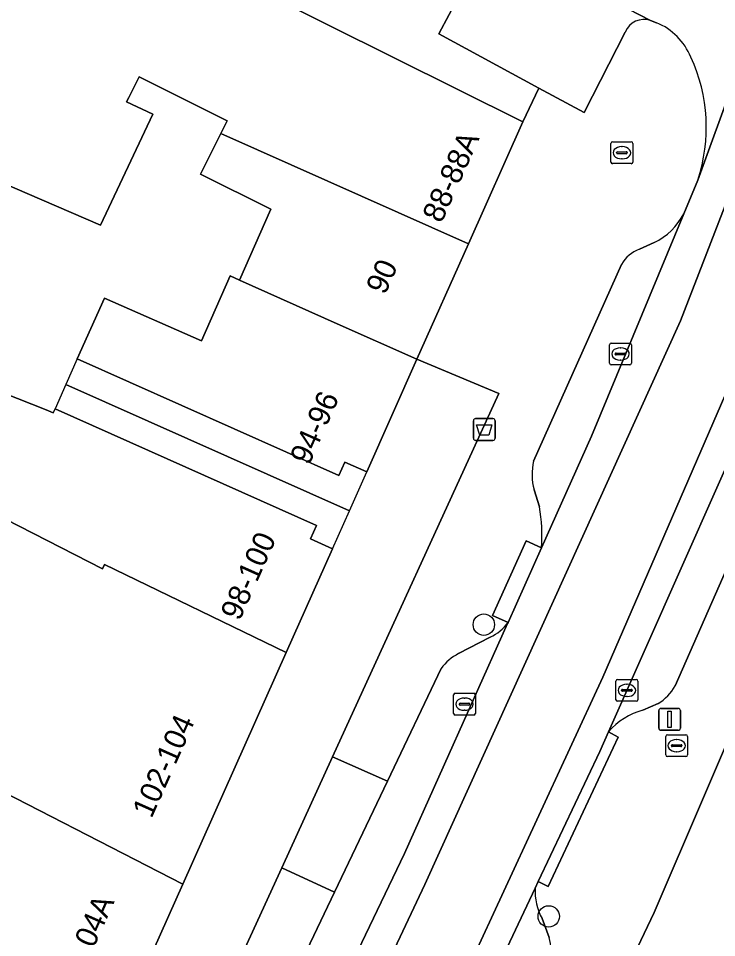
# Model space of a CAD drawing. Extents: x 160349 to 161355, y 381727 to 382854.
# Drawn here: x 160832.36 to 160864.31, y 382310.89 to 382352.95 of the extents above; entities that cross this region are included whole.
import ezdxf

# ---------------------------------------------------------------- set-up
doc = ezdxf.new("R2010")
doc.units = 0
for name, color, linetype in [('IMGEO_Afvalbak', 7, 'Continuous'), ('IMGEO_Boom', 7, 'Continuous'), ('IMGEO_Brandkraan', 7, 'Continuous'), ('IMGEO_Erf', 7, 'Continuous'), ('IMGEO_Kolk', 7, 'Continuous'), ('IMGEO_Lichtmast', 7, 'Continuous'), ('IMGEO_Pand', 7, 'Continuous'), ('IMGEO_Pand_nummerreeks', 7, 'Continuous'), ('IMGEO_Pand_overbouw', 7, 'Continuous'), ('IMGEO_Parkeervlak_open', 7, 'Continuous'), ('IMGEO_Rijbaan_lokaal_gesloten', 7, 'Continuous'), ('IMGEO_Rijbaan_lokaal_open', 7, 'Continuous'), ('IMGEO_Voetpad_open', 7, 'Continuous')]:
    doc.layers.add(name, color=color, linetype=linetype)

msp = doc.modelspace()

# ---------------------------------------------------------------- linework, layer by layer
at = {"layer": 'IMGEO_Afvalbak'}
for p, q in [((160853.179, 382333.741), (160853.179, 382334.541)), ((160853.179, 382334.541), (160853.179, 382333.741)), ((160853.279, 382334.641), (160854.069, 382334.641)), ((160854.069, 382334.641), (160853.279, 382334.641)), ((160854.169, 382334.541), (160854.169, 382333.741)), ((160854.169, 382333.741), (160854.169, 382334.541)), ((160854.069, 382333.641), (160853.279, 382333.641)), ((160853.279, 382333.641), (160854.069, 382333.641))]:
    msp.add_line(p, q, dxfattribs=at)
msp.add_lwpolyline([(160853.322, 382334.355), (160854.026, 382334.355), (160853.877, 382333.885), (160853.471, 382333.885), (160853.322, 382334.355)], dxfattribs=at)
for centre, start, end in [((160853.279, 382334.541), 90, 180), ((160853.279, 382334.541), 90, 180), ((160854.069, 382334.541), 0, 90), ((160854.069, 382334.541), 360, 90), ((160853.279, 382333.741), 180, 270), ((160853.279, 382333.741), 180, 270), ((160854.069, 382333.741), 270, 0), ((160854.069, 382333.741), 270, 0)]:
    msp.add_arc(centre, 0.1, start, end, dxfattribs=at)
at = {"layer": 'IMGEO_Boom'}
for centre in [(160853.654, 382325.214), (160856.624, 382311.862)]:
    msp.add_circle(centre, 0.489, dxfattribs=at)
at = {"layer": 'IMGEO_Brandkraan'}
for p, q in [((160859.472, 382346.381), (160859.472, 382347.233)), ((160859.547, 382347.307), (160860.399, 382347.307)), ((160860.473, 382347.233), (160860.473, 382346.381)), ((160859.731, 382346.801), (160859.731, 382346.813)), ((160860.169, 382346.764), (160859.771, 382346.764)), ((160859.774, 382346.85), (160860.172, 382346.85)), ((160859.96, 382347.087), (160859.985, 382347.087)), ((160860.215, 382346.813), (160860.215, 382346.801)), ((160860.399, 382346.307), (160859.547, 382346.307)), ((160859.983, 382346.527), (160859.958, 382346.527)), ((160861.978, 382319.251), (160861.978, 382320.103)), ((160862.053, 382320.177), (160862.905, 382320.177)), ((160862.466, 382319.957), (160862.491, 382319.957)), ((160862.979, 382320.103), (160862.979, 382319.251)), ((160862.237, 382319.671), (160862.237, 382319.683)), ((160862.675, 382319.634), (160862.277, 382319.634)), ((160862.28, 382319.72), (160862.678, 382319.72)), ((160862.489, 382319.397), (160862.464, 382319.397)), ((160862.721, 382319.683), (160862.721, 382319.671)), ((160862.905, 382319.177), (160862.053, 382319.177))]:
    msp.add_line(p, q, dxfattribs=at)
for points in [[(160859.472, 382346.381), (160859.472, 382347.233)], [(160859.547, 382347.307), (160860.399, 382347.307)], [(160860.473, 382347.233), (160860.473, 382346.381)], [(160860.399, 382346.307), (160859.547, 382346.307)], [(160861.978, 382319.251), (160861.978, 382320.103)], [(160862.053, 382320.177), (160862.905, 382320.177)], [(160862.979, 382320.103), (160862.979, 382319.251)], [(160862.905, 382319.177), (160862.053, 382319.177)]]:
    msp.add_lwpolyline(points, dxfattribs=at)
for centre, radius, start, end in [((160859.549, 382347.231), 0.0765, 91.552, 178.448), ((160859.549, 382347.231), 0.0765, 91.552, 178.448), ((160860.397, 382347.231), 0.0765, 1.552, 88.448), ((160860.397, 382347.231), 0.0765, 1.552, 88.448), ((160859.771, 382346.81), 0.0403, 85.8775, 175.7526), ((160859.768, 382346.8), 0.0366, 178.938, 274.7102), ((160860.172, 382346.807), 0.043, 264.8664, 352.4533), ((160860.176, 382346.812), 0.0386, 1.7309, 96.639), ((160859.549, 382346.383), 0.0765, 181.552, 268.448), ((160859.549, 382346.383), 0.0765, 181.552, 268.448), ((160860.397, 382346.383), 0.0765, 271.552, 358.448), ((160860.397, 382346.383), 0.0765, 271.552, 358.448), ((160862.055, 382320.101), 0.0765, 91.552, 178.448), ((160862.055, 382320.101), 0.0765, 91.552, 178.448), ((160862.903, 382320.101), 0.0765, 1.552, 88.448), ((160862.903, 382320.101), 0.0765, 1.552, 88.448), ((160862.277, 382319.68), 0.0403, 85.8775, 175.7526), ((160862.274, 382319.67), 0.0366, 178.938, 274.7102), ((160862.678, 382319.677), 0.043, 264.8664, 352.4533), ((160862.682, 382319.682), 0.0386, 1.7309, 96.639), ((160862.055, 382319.253), 0.0765, 181.552, 268.448), ((160862.055, 382319.253), 0.0765, 181.552, 268.448), ((160862.903, 382319.253), 0.0765, 271.552, 358.448), ((160862.903, 382319.253), 0.0765, 271.552, 358.448)]:
    msp.add_arc(centre, radius, start, end, dxfattribs=at)
for centre, major_axis, ratio, start_param, end_param in [((160859.959, 382346.807), (-0.387, 0.002), 0.722429, 4.712389, 7.853982), ((160859.984, 382346.807), (-0.39, 0.002), 0.717154, 1.570796, 4.712389), ((160862.465, 382319.677), (-0.387, 0.002), 0.722429, 4.712389, 7.853982), ((160862.49, 382319.677), (-0.39, 0.002), 0.717154, 1.570796, 4.712389)]:
    msp.add_ellipse(centre, major_axis=major_axis, ratio=ratio, start_param=start_param, end_param=end_param, dxfattribs=at)
at = {"layer": 'IMGEO_Erf'}
for points in [[(160840.283, 382305.069), (160844.409, 382314.087), (160846.734, 382319.167), (160854.342, 382335.793), (160850.594, 382337.355), (160848.294, 382332.2), (160847.289, 382332.648), (160847.015, 382332.033), (160835.051, 382337.37), (160836.291, 382340.148), (160840.739, 382338.197), (160842.045, 382341.175), (160842.476, 382340.982), (160843.901, 382344.231), (160840.694, 382345.827), (160841.622, 382347.689), (160841.911, 382348.27), (160837.883, 382350.276), (160837.402, 382349.342), (160837.297, 382349.138), (160838.502, 382348.57), (160836.117, 382343.497), (160829.49, 382346.35)], [(160824.349, 382338.702), (160833.629, 382335.048), (160833.951, 382334.904), (160834.033, 382335.087), (160845.996, 382329.75), (160845.721, 382329.134), (160846.726, 382328.686), (160844.607, 382323.937), (160839.877, 382313.337), (160837.197, 382307.331), (160832.747, 382309.61), (160830.326, 382310.85)], [(160872.549, 382337.919), (160861.447, 382312.039), (160855.676, 382299.934)]]:
    msp.add_lwpolyline(points, dxfattribs=at)
at = {"layer": 'IMGEO_Kolk'}
for p, q in [((160859.408, 382337.172), (160859.408, 382338.024)), ((160859.483, 382338.098), (160860.335, 382338.098)), ((160859.896, 382337.878), (160859.921, 382337.878)), ((160860.409, 382338.024), (160860.409, 382337.172)), ((160859.667, 382337.592), (160859.667, 382337.604)), ((160860.105, 382337.555), (160859.707, 382337.555)), ((160859.71, 382337.641), (160860.108, 382337.641)), ((160860.151, 382337.604), (160860.151, 382337.592)), ((160860.335, 382337.098), (160859.483, 382337.098)), ((160859.919, 382337.318), (160859.894, 382337.318)), ((160859.775, 382322.707), (160860.627, 382322.707)), ((160859.7, 382321.781), (160859.7, 382322.633)), ((160860.188, 382322.487), (160860.213, 382322.487)), ((160860.701, 382322.633), (160860.701, 382321.781)), ((160852.269, 382321.149), (160852.269, 382322.001)), ((160852.344, 382322.075), (160853.196, 382322.075)), ((160853.27, 382322.001), (160853.27, 382321.149)), ((160859.959, 382322.201), (160859.959, 382322.213)), ((160860.397, 382322.164), (160859.999, 382322.164)), ((160860.002, 382322.25), (160860.4, 382322.25)), ((160860.211, 382321.927), (160860.186, 382321.927)), ((160860.443, 382322.213), (160860.443, 382322.201)), ((160852.528, 382321.569), (160852.528, 382321.581)), ((160852.966, 382321.532), (160852.568, 382321.532)), ((160852.571, 382321.618), (160852.969, 382321.618)), ((160852.757, 382321.855), (160852.782, 382321.855)), ((160853.012, 382321.581), (160853.012, 382321.569)), ((160860.627, 382321.707), (160859.775, 382321.707)), ((160853.196, 382321.075), (160852.344, 382321.075)), ((160852.78, 382321.295), (160852.755, 382321.295))]:
    msp.add_line(p, q, dxfattribs=at)
for points in [[(160859.408, 382337.172), (160859.408, 382338.024)], [(160859.483, 382338.098), (160860.335, 382338.098)], [(160860.409, 382338.024), (160860.409, 382337.172)], [(160860.335, 382337.098), (160859.483, 382337.098)], [(160859.775, 382322.707), (160860.627, 382322.707)], [(160859.7, 382321.781), (160859.7, 382322.633)], [(160860.701, 382322.633), (160860.701, 382321.781)], [(160852.269, 382321.149), (160852.269, 382322.001)], [(160852.344, 382322.075), (160853.196, 382322.075)], [(160853.27, 382322.001), (160853.27, 382321.149)], [(160860.627, 382321.707), (160859.775, 382321.707)], [(160853.196, 382321.075), (160852.344, 382321.075)]]:
    msp.add_lwpolyline(points, dxfattribs=at)
for centre, radius, start, end in [((160859.485, 382338.022), 0.0765, 91.552, 178.448), ((160859.485, 382338.022), 0.0765, 91.552, 178.448), ((160860.333, 382338.022), 0.0765, 1.552, 88.448), ((160860.333, 382338.022), 0.0765, 1.552, 88.448), ((160859.707, 382337.601), 0.0403, 85.8775, 175.7526), ((160859.704, 382337.591), 0.0366, 178.938, 274.7102), ((160860.108, 382337.598), 0.043, 264.8664, 352.4533), ((160860.112, 382337.603), 0.0386, 1.7309, 96.639), ((160859.485, 382337.174), 0.0765, 181.552, 268.448), ((160859.485, 382337.174), 0.0765, 181.552, 268.448), ((160860.333, 382337.174), 0.0765, 271.552, 358.448), ((160860.333, 382337.174), 0.0765, 271.552, 358.448), ((160859.777, 382322.631), 0.0765, 91.552, 178.448), ((160859.777, 382322.631), 0.0765, 91.552, 178.448), ((160860.625, 382322.631), 0.0765, 1.552, 88.448), ((160860.625, 382322.631), 0.0765, 1.552, 88.448), ((160852.346, 382321.999), 0.0765, 91.552, 178.448), ((160852.346, 382321.999), 0.0765, 91.552, 178.448), ((160853.194, 382321.999), 0.0765, 1.552, 88.448), ((160853.194, 382321.999), 0.0765, 1.552, 88.448), ((160859.999, 382322.21), 0.0403, 85.8775, 175.7526), ((160859.996, 382322.2), 0.0366, 178.938, 274.7102), ((160860.4, 382322.207), 0.043, 264.8664, 352.4533), ((160860.404, 382322.212), 0.0386, 1.7309, 96.639), ((160852.568, 382321.578), 0.0403, 85.8775, 175.7526), ((160852.565, 382321.568), 0.0366, 178.938, 274.7102), ((160852.969, 382321.575), 0.043, 264.8664, 352.4533), ((160852.973, 382321.58), 0.0386, 1.7309, 96.639), ((160859.777, 382321.783), 0.0765, 181.552, 268.448), ((160859.777, 382321.783), 0.0765, 181.552, 268.448), ((160860.625, 382321.783), 0.0765, 271.552, 358.448), ((160860.625, 382321.783), 0.0765, 271.552, 358.448), ((160852.346, 382321.151), 0.0765, 181.552, 268.448), ((160852.346, 382321.151), 0.0765, 181.552, 268.448), ((160853.194, 382321.151), 0.0765, 271.552, 358.448), ((160853.194, 382321.151), 0.0765, 271.552, 358.448)]:
    msp.add_arc(centre, radius, start, end, dxfattribs=at)
for centre, major_axis, ratio, start_param, end_param in [((160859.895, 382337.598), (-0.387, 0.002), 0.722429, 4.712389, 7.853982), ((160859.92, 382337.598), (-0.39, 0.002), 0.717154, 1.570796, 4.712389), ((160860.187, 382322.207), (-0.387, 0.002), 0.722429, 4.712389, 7.853982), ((160860.212, 382322.207), (-0.39, 0.002), 0.717154, 1.570796, 4.712389), ((160852.756, 382321.575), (-0.387, 0.002), 0.722429, 4.712389, 7.853982), ((160852.781, 382321.575), (-0.39, 0.002), 0.717154, 1.570796, 4.712389)]:
    msp.add_ellipse(centre, major_axis=major_axis, ratio=ratio, start_param=start_param, end_param=end_param, dxfattribs=at)
at = {"layer": 'IMGEO_Lichtmast'}
for p, q in [((160861.661, 382320.479), (160861.661, 382321.279)), ((160861.661, 382321.279), (160861.661, 382320.479)), ((160861.761, 382321.379), (160862.551, 382321.379)), ((160862.551, 382321.379), (160861.761, 382321.379)), ((160862.651, 382321.279), (160862.651, 382320.479)), ((160862.651, 382320.479), (160862.651, 382321.279)), ((160862.551, 382320.379), (160861.761, 382320.379)), ((160861.761, 382320.379), (160862.551, 382320.379))]:
    msp.add_line(p, q, dxfattribs=at)
msp.add_lwpolyline([(160862.081, 382321.254), (160862.231, 382321.254), (160862.231, 382320.504), (160862.081, 382320.504), (160862.081, 382321.254)], dxfattribs=at)
for centre, start, end in [((160861.761, 382321.279), 90, 180), ((160861.761, 382321.279), 90, 180), ((160862.551, 382321.279), 0, 90), ((160862.551, 382321.279), 360, 90), ((160861.761, 382320.479), 180, 270), ((160861.761, 382320.479), 180, 270), ((160862.551, 382320.479), 270, 0), ((160862.551, 382320.479), 270, 0)]:
    msp.add_arc(centre, 0.1, start, end, dxfattribs=at)
at = {"layer": 'IMGEO_Pand'}
for points in [[(160840.624, 382355.601), (160834.522, 382358.737), (160831.084, 382352.062), (160828.387, 382346.825), (160829.49, 382346.35), (160836.117, 382343.497), (160838.502, 382348.57), (160837.297, 382349.138), (160837.402, 382349.342), (160837.883, 382350.276), (160841.911, 382348.27), (160841.622, 382347.689), (160852.95, 382342.635), (160855.442, 382348.219)], [(160824.13, 382333.943), (160822.641, 382334.707), (160816.462, 382337.876), (160812.151, 382340.084), (160814.082, 382344.143), (160813.558, 382344.41), (160808.311, 382347.085), (160800.669, 382350.981), (160798.222, 382346.149), (160798.32, 382346.099), (160793.525, 382336.676), (160797.976, 382334.397), (160806.047, 382330.263), (160807.336, 382329.603), (160812.895, 382326.627), (160819.899, 382323.04), (160820.741, 382322.676), (160823.62, 382321.432), (160829.477, 382318.678), (160839.877, 382313.337), (160844.607, 382323.937), (160836.29, 382327.967), (160836.2, 382327.763)], [(160852.95, 382342.635), (160841.622, 382347.689), (160840.694, 382345.827), (160843.901, 382344.231), (160842.476, 382340.982), (160846.946, 382338.985), (160850.594, 382337.355)], [(160850.594, 382337.355), (160846.946, 382338.985), (160842.476, 382340.982), (160842.045, 382341.175), (160840.739, 382338.197), (160836.291, 382340.148), (160835.051, 382337.37), (160847.015, 382332.033), (160847.289, 382332.648), (160848.294, 382332.2)], [(160834.033, 382335.087), (160833.951, 382334.904), (160833.629, 382335.048), (160824.349, 382338.702), (160822.641, 382334.707), (160824.13, 382333.943), (160836.2, 382327.763), (160836.29, 382327.967), (160844.607, 382323.937), (160846.726, 382328.686), (160845.721, 382329.134), (160845.996, 382329.75)], [(160839.877, 382313.337), (160829.477, 382318.678), (160827.951, 382315.694), (160826.934, 382315.169), (160825.98, 382313.304), (160826.098, 382312.071), (160829.944, 382310.103), (160830.326, 382310.85), (160832.747, 382309.61), (160837.197, 382307.331)]]:
    msp.add_lwpolyline(points, close=True, dxfattribs=at)
at = {"layer": 'IMGEO_Pand_overbouw'}
for points in [[(160835.051, 382337.37), (160834.534, 382336.21), (160847.502, 382330.425), (160848.294, 382332.2), (160847.289, 382332.648), (160847.015, 382332.033)], [(160834.534, 382336.21), (160834.033, 382335.087), (160845.996, 382329.75), (160845.721, 382329.134), (160846.726, 382328.686), (160847.502, 382330.425)]]:
    msp.add_lwpolyline(points, close=True, dxfattribs=at)
at = {"layer": 'IMGEO_Parkeervlak_open'}
for points in [[(160861.281, 382352.862), (160853.229, 382357.027)], [(160853.479, 382355.802), (160851.599, 382352.248), (160856.177, 382349.769), (160858.25, 382348.646), (160860.123, 382352.329)], [(160856.293, 382328.731), (160858.578, 382333.835), (160862.813, 382344.017)], [(160861.443, 382342.7), (160860.772, 382342.39)], [(160859.952, 382341.698), (160855.933, 382332.702)], [(160867.708, 382339.101), (160859.359, 382320.315)], [(160862.412, 382322.418), (160868.227, 382335.619)], [(160855.956, 382331.381), (160856.203, 382330.609)], [(160844.333, 382302.883), (160850.03, 382314.742), (160854.74, 382325.262), (160854.763, 382325.314)], [(160853.948, 382324.648), (160852.497, 382323.888)], [(160851.702, 382323.208), (160849.243, 382318.052), (160846.821, 382312.974), (160843.818, 382306.679)], [(160860.923, 382321.302), (160861.631, 382321.599)], [(160856.008, 382313.16), (160849.068, 382298.447)], [(160856.648, 382310.894), (160856.323, 382311.767)]]:
    msp.add_lwpolyline(points, dxfattribs=at)
for centre, radius, start, end in [((160860.991, 382351.968), 0.94, 72.0019, 157.4291), ((160860.136, 382345.431), 3.028, 295.5793, 332.1607), ((160861.264, 382340.975), 1.498, 109.1763, 151.1459), ((160858.453, 382332.085), 2.594, 166.2459, 195.7491), ((160848.449, 382329.296), 7.864, 355.8783, 9.6091), ((160853.117, 382326.497), 2.027, 294.2063, 324.3036), ((160853.546, 382321.856), 2.287, 117.3181, 143.7657), ((160860.442, 382323.515), 2.255, 301.8266, 330.8945), ((160861.792, 382318.193), 3.229, 105.6116, 138.8983), ((160858.435, 382312.977), 2.434, 175.681, 209.8031), ((160854.649, 382310.321), 2.079, 346.2719, 15.9853)]:
    msp.add_arc(centre, radius, start, end, dxfattribs=at)
at = {"layer": 'IMGEO_Rijbaan_lokaal_gesloten'}
for points in [[(160870.039, 382363.675), (160863.441, 382345.553), (160862.813, 382344.017), (160858.578, 382333.835), (160856.293, 382328.731), (160854.763, 382325.314), (160854.74, 382325.262), (160850.03, 382314.742), (160844.333, 382302.883), (160842.376, 382298.812), (160838.167, 382290.047), (160826.186, 382266.882), (160817.325, 382250.962), (160805.521, 382230.961), (160798.28, 382218.963), (160786.323, 382199.028)], [(160798.503, 382206.859), (160798.962, 382207.633), (160800.434, 382210.12), (160801.83, 382212.468), (160804.931, 382217.699), (160806.44, 382220.243), (160820.447, 382243.859), (160823.843, 382250), (160824.345, 382250.697), (160824.515, 382250.932), (160833.193, 382266.844), (160846.051, 382292.081), (160846.152, 382292.278), (160846.237, 382292.445), (160848.99, 382298.282), (160849.068, 382298.447), (160856.008, 382313.16), (160856.147, 382313.455), (160858.959, 382319.416), (160859.359, 382320.315), (160867.708, 382339.101), (160867.955, 382339.717), (160869.629, 382343.884), (160875.162, 382358.523)], [(160792.985, 382200.423), (160805.748, 382221.628), (160816.567, 382239.989), (160824.699, 382254.022), (160830.666, 382264.645), (160835.649, 382274.12), (160839.879, 382282.612), (160846.567, 382296.087), (160853.059, 382309.759), (160859.092, 382322.809), (160864.338, 382334.874), (160869.059, 382345.759), (160870.928, 382350.579), (160873.42, 382357.694)], [(160873.42, 382357.694), (160870.928, 382350.579), (160869.059, 382345.759), (160864.338, 382334.874), (160859.092, 382322.809), (160853.059, 382309.759), (160846.567, 382296.087), (160839.879, 382282.612), (160835.649, 382274.12), (160830.666, 382264.645), (160824.699, 382254.022), (160816.567, 382239.989), (160805.748, 382221.628), (160792.985, 382200.423)], [(160784.239, 382192.537), (160812.989, 382240.37), (160826.989, 382265.037), (160837.239, 382284.953), (160845.281, 382301.287), (160850.947, 382313.328), (160862.656, 382339.12), (160868.864, 382355.162)], [(160868.864, 382355.162), (160862.656, 382339.12), (160850.947, 382313.328), (160845.281, 382301.287), (160837.239, 382284.953), (160826.989, 382265.037), (160812.989, 382240.37), (160784.239, 382192.537)]]:
    msp.add_lwpolyline(points, dxfattribs=at)
at = {"layer": 'IMGEO_Rijbaan_lokaal_open'}
for points in [[(160799.55, 382384.598), (160800.225, 382384.222), (160803.917, 382382.318), (160805.403, 382381.588), (160815.833, 382376.227), (160816.846, 382375.72), (160822.824, 382372.668), (160823.097, 382372.543), (160827.651, 382370.194), (160827.802, 382370.103), (160831.471, 382368.287), (160832.99, 382367.513), (160836.667, 382365.599), (160837.274, 382365.279), (160844.809, 382361.38), (160844.984, 382361.288), (160850.841, 382358.243), (160853.229, 382357.027), (160861.281, 382352.862), (160861.561, 382352.753)], [(160863.441, 382345.553), (160870.039, 382363.675)]]:
    msp.add_lwpolyline(points, dxfattribs=at)
for centre, radius, start, end in [((160860.474, 382350.102), 2.865, 22.1847, 67.7056), ((160856.201, 382347.974), 7.634, 341.5147, 24.8686)]:
    msp.add_arc(centre, radius, start, end, dxfattribs=at)
at = {"layer": 'IMGEO_Voetpad_open'}
for points in [[(160802.752, 382381.834), (160800.936, 382378.337), (160800.092, 382378.799), (160798.877, 382376.326), (160812.061, 382369.528), (160812.35, 382370.094), (160819.927, 382366.214), (160823.776, 382364.261), (160834.522, 382358.737), (160840.624, 382355.601), (160855.442, 382348.219), (160856.177, 382349.769), (160851.599, 382352.248), (160853.479, 382355.802)], [(160835.239, 382258.802), (160836.402, 382261.505), (160853.77, 382296.133), (160855.676, 382299.934), (160861.447, 382312.039), (160872.549, 382337.919), (160872.943, 382338.838), (160873.33, 382339.739), (160873.965, 382341.274), (160873.995, 382341.347), (160880.149, 382356.225)], [(160861.561, 382352.753), (160861.281, 382352.862)], [(160860.123, 382352.329), (160858.25, 382348.646), (160856.177, 382349.769), (160855.442, 382348.219), (160852.95, 382342.635), (160850.594, 382337.355), (160854.342, 382335.793), (160846.734, 382319.167), (160849.243, 382318.052), (160851.702, 382323.208)], [(160862.813, 382344.017), (160863.441, 382345.553)], [(160860.772, 382342.39), (160861.443, 382342.7)], [(160855.933, 382332.702), (160859.952, 382341.698)], [(160868.227, 382335.619), (160862.412, 382322.418)], [(160856.203, 382330.609), (160855.956, 382331.381)], [(160854.763, 382325.314), (160854.053, 382325.64), (160855.587, 382329.052), (160856.293, 382328.731)], [(160852.497, 382323.888), (160853.948, 382324.648)], [(160861.631, 382321.599), (160860.923, 382321.302)], [(160859.359, 382320.315), (160859.794, 382320.065), (160856.598, 382313.24), (160856.147, 382313.455), (160856.008, 382313.16)], [(160843.818, 382306.679), (160846.821, 382312.974), (160844.409, 382314.087), (160840.283, 382305.069), (160838.339, 382300.821), (160828.746, 382282.08), (160815.558, 382257.479), (160811.234, 382250), (160794.573, 382221.181), (160772.407, 382184.113), (160770.967, 382181.708)], [(160856.323, 382311.767), (160856.648, 382310.894)]]:
    msp.add_lwpolyline(points, dxfattribs=at)
for points in [[(160856.293, 382328.731), (160855.587, 382329.052), (160854.053, 382325.64), (160854.763, 382325.314)], [(160859.359, 382320.315), (160858.959, 382319.416), (160856.147, 382313.455), (160856.598, 382313.24), (160859.794, 382320.065)], [(160846.734, 382319.167), (160844.409, 382314.087), (160846.821, 382312.974), (160849.243, 382318.052)]]:
    msp.add_lwpolyline(points, close=True, dxfattribs=at)
for centre, radius, start, end in [((160860.991, 382351.968), 0.94, 72.0019, 157.4291), ((160860.474, 382350.102), 2.865, 22.1847, 67.7056), ((160856.201, 382347.974), 7.634, 341.5147, 24.8686), ((160860.136, 382345.431), 3.028, 295.5793, 332.1607), ((160861.264, 382340.975), 1.498, 109.1763, 151.1459), ((160858.453, 382332.085), 2.594, 166.2459, 195.7491), ((160848.449, 382329.296), 7.864, 355.8783, 9.6091), ((160853.117, 382326.497), 2.027, 294.2063, 324.3036), ((160853.546, 382321.856), 2.287, 117.3181, 143.7657), ((160860.442, 382323.515), 2.255, 301.8266, 330.8945), ((160861.792, 382318.193), 3.229, 105.6116, 138.8983), ((160858.435, 382312.977), 2.434, 175.681, 209.8031), ((160854.649, 382310.321), 2.079, 346.2719, 15.9853)]:
    msp.add_arc(centre, radius, start, end, dxfattribs=at)

# ---------------------------------------------------------------- texts
at = {"layer": 'IMGEO_Pand_nummerreeks'}
for s, rotation, p in [('88-88A', 65.9474, (160851.714, 382343.546)), ('90', 65.9532, (160849.135, 382340.27)), ('94-96', 65.9532, (160845.657, 382332.472)), ('98-100', 65.9527, (160842.477, 382325.347)), ('102-104', 65.9532, (160838.446, 382316.315)), ('104A', 65.9532, (160835.496, 382309.702))]:
    msp.add_text(s, height=1, rotation=rotation, dxfattribs=at).set_placement(p)

doc.saveas('drawing.dxf')
